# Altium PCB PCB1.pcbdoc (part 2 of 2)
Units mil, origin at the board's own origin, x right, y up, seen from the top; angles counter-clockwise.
Board outline 1377.9 x 2559.1 mil, 4 copper layers (Top Layer, Inner1, Inner2, Bottom Layer), stack 62.5 mil thick; 243 components, 192 nets, 1028 pads, 96 vias.
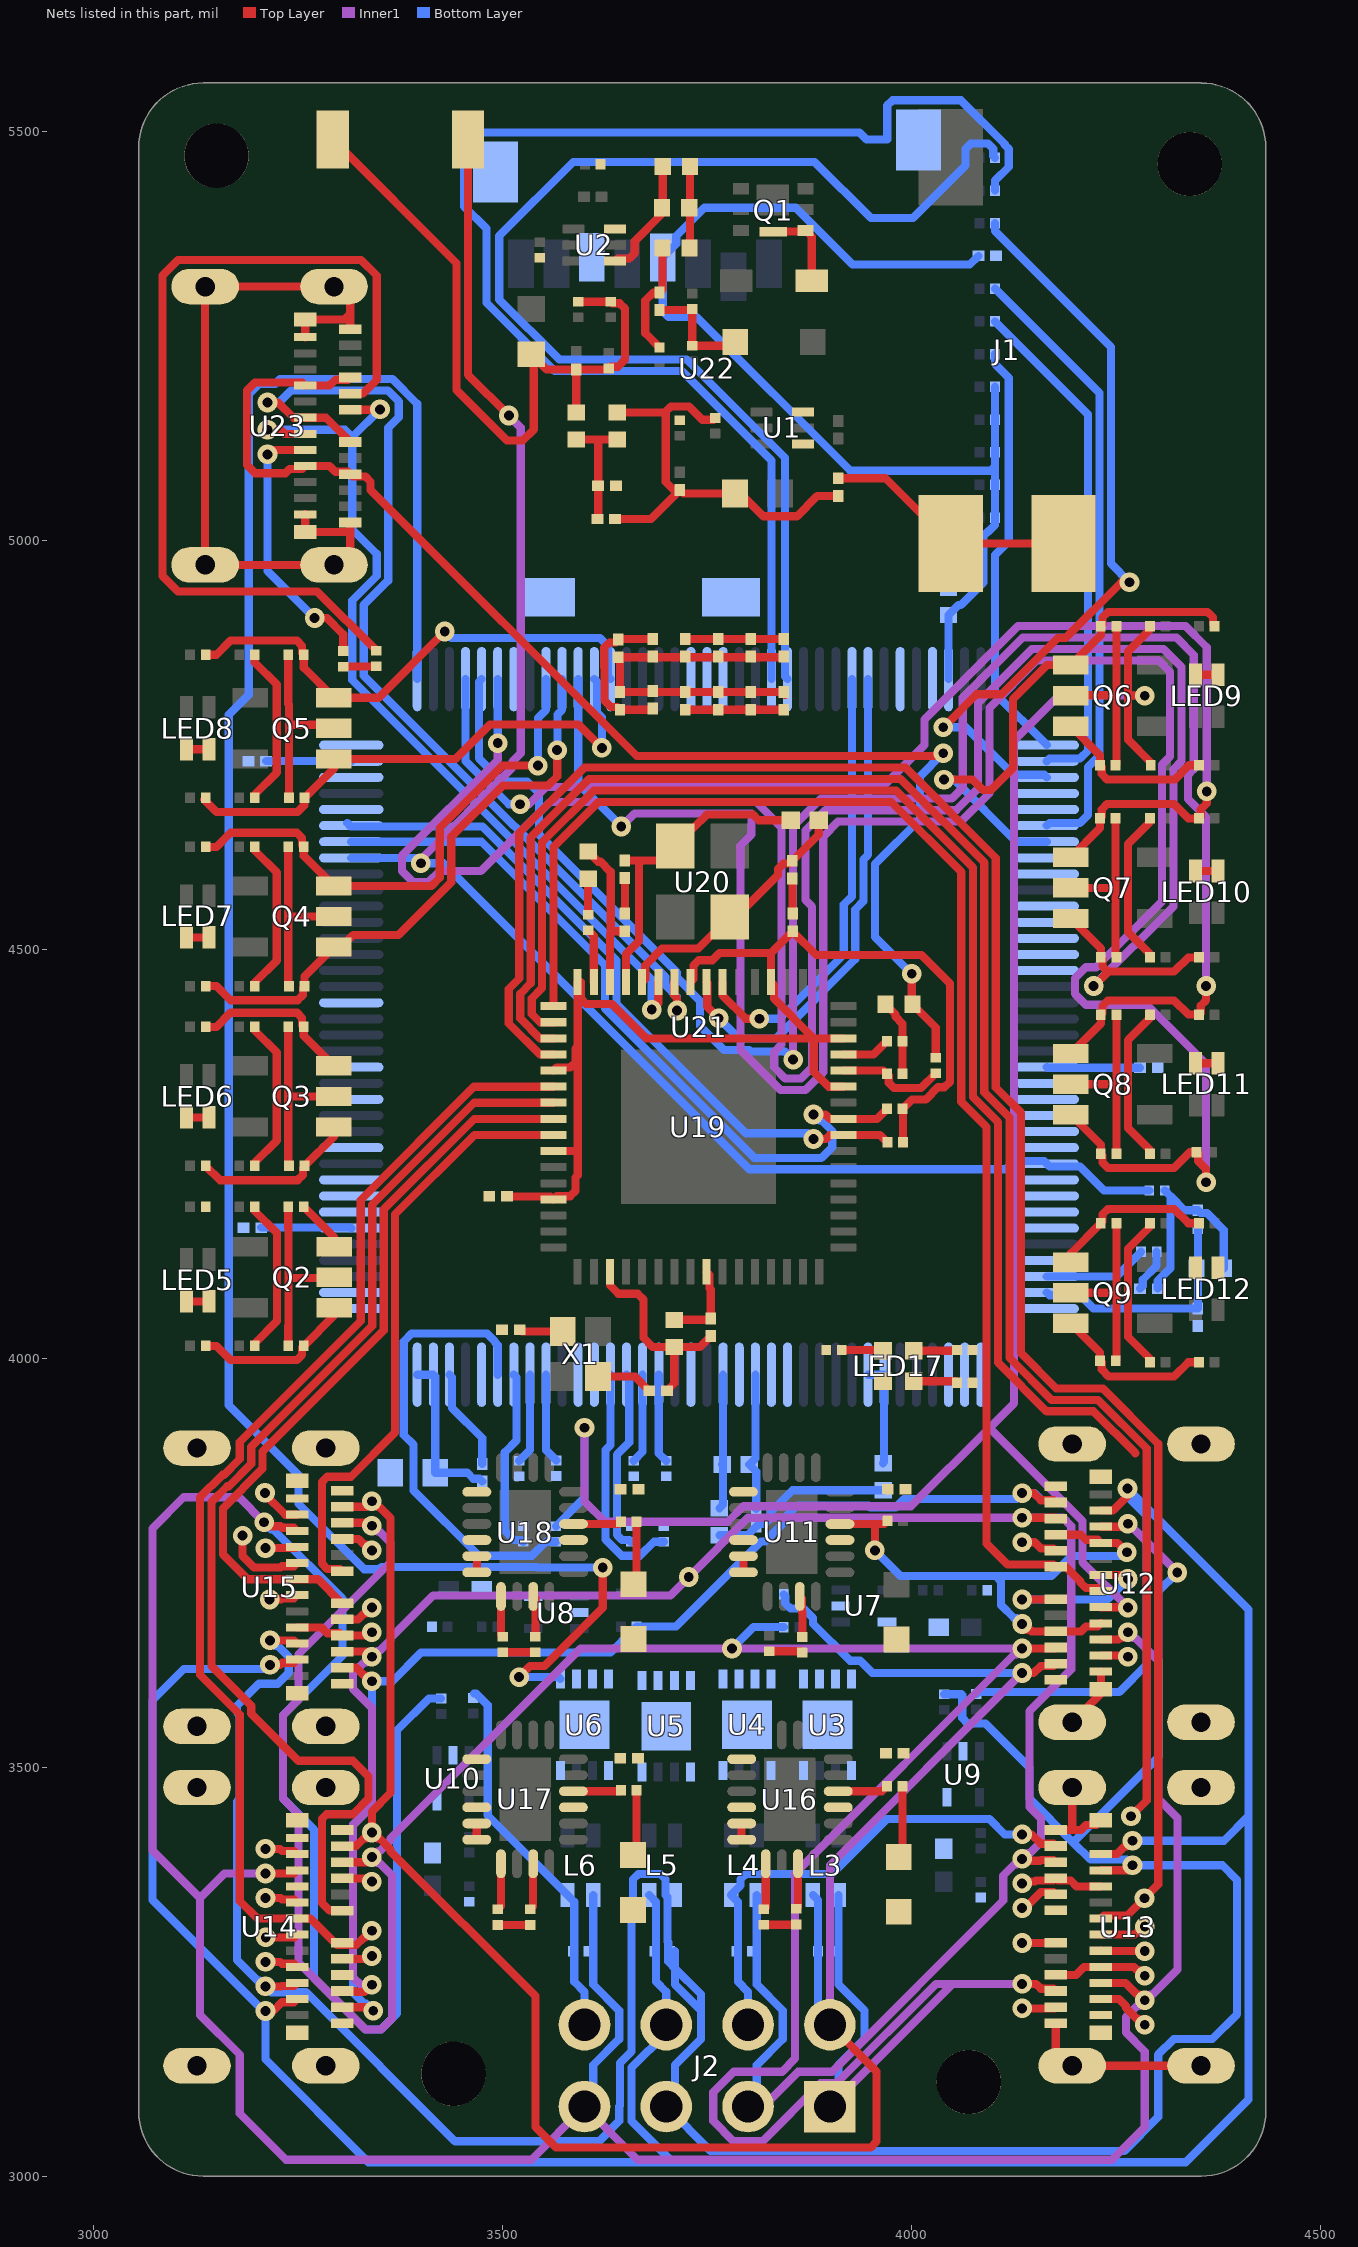
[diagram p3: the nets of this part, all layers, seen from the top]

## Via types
v1: diameter 24, hole 12, Top Layer to Bottom Layer, 96 vias

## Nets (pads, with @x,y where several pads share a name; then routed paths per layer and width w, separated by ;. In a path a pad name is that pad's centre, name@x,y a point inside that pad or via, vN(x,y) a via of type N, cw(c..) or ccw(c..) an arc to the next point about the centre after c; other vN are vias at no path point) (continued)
$1N25057: R81.2 U11.4 U12.A4 U12.A9 U12.B4 U12.B9 | length 699.3
  Top Layer w10: U11.4@3912.2,3797.2 3952.6,3797.2 ; v1(3954.8,3765) 3954.8,3795.1 3952.6,3797.2 ; R81.2@3970.3,3801.4 3966.2,3797.2 3952.6,3797.2 ; v1(4134.8,3675) 4141.8,3668 4144.3,3668 4146.3,3666 U12.A4@4176,3666 4206.8,3666 4212.8,3672 4227.3,3672 U12.B9@4231.1,3675.8 ; U12.A9@4176,3784.1 4206.6,3784.1 4212.8,3778 4227.3,3778 U12.B4@4231.1,3774.2 4251.3,3774.2 v1(4262.9,3762.7)
  Bottom Layer w10: v1(3954.8,3765) 3986.2,3733.6 4102.8,3733.6 ; v1(4134.8,3675) 4127.8,3682 4125.2,3682 4109.2,3698 4109.2,3727.2 4102.8,3733.6 ; v1(4262.9,3762.7) 4258.2,3758 4195,3758 4170.6,3733.6 4102.8,3733.6
$1N25065: R84.2 U13.A4 U13.A9 U13.B4 U13.B9 U16.4 | length 282.5
  Top Layer w10: U16.4@3910,3470.5 3963.4,3470.5 R84.2@3969.6,3476.7 ; v1(4134.8,3357.8) 4137,3360 4150.6,3360 4151.9,3361.3 4157.6,3361.3 4157.7,3361.3 4173.2,3361.3 U13.A9@4176,3364.1 4178.8,3361.3 4194.3,3361.3 4201.4,3354.2 U13.B4@4231.1,3354.2 ; U13.A4@4176,3246 4200.8,3246 4210.6,3255.8 U13.B9@4231.1,3255.8 4271.5,3255.8 4275.2,3252 4277.8,3252 v1(4284.8,3245)
$1N25090: LED14.1 R84.1 | length 88.4
  Top Layer w10: LED14.1@3984.1,3390.2 3988.6,3394.7 R84.1@3988.6,3476.7
$1N25091: R83.1 U16.17 | length 56.7
  Top Layer w10: R83.1@3819.1,3326.2 3821.4,3328.5 U16.17@3821.4,3381.9
$1N25094: R90.2 U15.A4 U15.A9 U15.B4 U15.B9 U18.4 | length 237.7
  Top Layer w10: v1(3209.7,3767.8) 3247,3767.8 U15.B9@3248.4,3769.2 ; U15.B4@3248.4,3670.8 3278.1,3670.8 3285.2,3663.7 3300.7,3663.7 U15.A9@3303.5,3660.9 3335.6,3660.9 v1(3339.8,3665) ; U15.A4@3303.5,3779 3323.3,3779 3330.2,3772 3332.8,3772 v1(3339.8,3765) ; U18.4@3586.3,3797.3 3641.5,3797.3 R90.2@3644.3,3800
$1N25095: R87.2 U14.A4 U14.A9 U14.B4 U14.B9 U17.4 | length 138.1
  Top Layer w10: v1(3209.7,3261.9) 3227.8,3261.9 3230.1,3259.6 3244.6,3259.6 U14.B4@3248.4,3255.8 ; U14.A4@3303.5,3364 3335.8,3364 v1(3339.8,3360) ; U17.4@3586.2,3470.5 3642.9,3470.5 R87.2@3644.5,3472
$1N25144: LED16.1 R90.1 | length 77.9
  Top Layer w10: LED16.1@3659.8,3723.5 3663.3,3727 R90.1@3663.3,3800
$1N25145: LED15.1 R87.1 | length 81.4
  Top Layer w10: LED15.1@3659.2,3392.4 3663.5,3396.7 R87.1@3663.5,3472
$1N25146: R89.1 U18.17 | length 50.1
  Top Layer w10: U18.17@3497.7,3708.7 3497.7,3661.6 R89.1@3499.8,3659.5
$1N25147: R86.1 U17.17 | length 57.6
  Top Layer w10: R86.1@3493.5,3326.1 3497.7,3330.2 U17.17@3497.7,3381.9
$1N25148: LED17.4 R93.1 | length 50.9
  Top Layer w10: R93.1@3914.3,4010 3963.9,4010 LED17.4@3964.9,4009.1
$1N25149: LED17.3 R92.1 | length 53.3
  Top Layer w10: LED17.3@4002.3,4009.1 4054.3,4009.1 R92.1@4055.3,4010
$1N25150: LED17.2 R91.2 | length 53.7
  Top Layer w10: LED17.2@4002.3,3971.7 4053.6,3971.7 R91.2@4055.3,3970
$1N25179: R94.1 U21.28 | length 110
  Bottom Layer w10: U21.28@3552.8,3979.8 3552.8,3887.5 R94.1@3565.3,3875
$1N25180: R95.1 U21.29 | length 110.8
  Bottom Layer w10: R95.1@3519.8,3874.5 3533.1,3887.8 U21.29@3533.1,3979.8
$1N25181: R96.1 U21.30 | length 226
  Bottom Layer w10: U21.30@3513.4,3979.8 3516.6,3976.6 3516.6,3899.2 3502.4,3885 3502.4,3789 3513.8,3777.6 3522.7,3777.6 R96.1@3524.8,3775.5
$1N25182: R97.1 U21.31 | length 563.1
  Bottom Layer w10: U21.31@3493.7,3979.8 3493.7,4016.2 3490.5,4019.4 3490.5,4020.5 3480.8,4030.2 3388.4,4030.2 3378.8,4020.5 3378.8,3906.2 3390.6,3894.4 3390.6,3838.4 3470.5,3758.5 3535.7,3758.5 3552.6,3775.5 R97.1@3564.8,3775.5
$1N25226: R98.1 U21.21 | length 109.1
  Bottom Layer w10: U21.21@3690.6,3979.8 3690.6,3883.7 R98.1@3699.8,3874.5
$1N25227: R99.1 U21.22 | length 109.9
  Bottom Layer w10: R99.1@3659.8,3874.5 3670.9,3885.6 U21.22@3670.9,3979.8
$1N25228: R100.1 U21.23 | length 224.3
  Bottom Layer w10: U21.23@3651.2,3979.8 3654.4,3976.6 3654.4,3897 3639.4,3882 3639.4,3784 3645.8,3777.6 3654.7,3777.6 R100.1@3656.8,3775.5
$1N25229: R101.1 U21.24 | length 290.8
  Bottom Layer w10: U21.24@3631.5,3979.8 3631.5,3893.9 3625.4,3887.8 3625.4,3778.2 3645,3758.5 3667.7,3758.5 3684.6,3775.5 R101.1@3696.8,3775.5
$1N25245: R102.1 U21.142 | length 127.7
  Bottom Layer w10: U21.142@4165,4099.9 4250.1,4099.9 R102.1@4280.3,4130
$1N25278: C44.1
$1N25293: R115.1 U23.A5 | length 1111.4
  Top Layer w10: U23.A5@3313.5,5179.3 3329.1,5179.3 3345.8,5196 3345.8,5323.6 3326.7,5342.7 3102.8,5342.7 3083.7,5323.6 3083.7,4956.4 3102.8,4937.3 3273,4937.3 R115.1@3345.3,4865
$1N25294: R116.2 U23.B5 | length 329.1
  Top Layer w10: v1(3212.2,5105) 3217.7,5110.5 U23.B5@3258.4,5110.5 ; v1(3269.8,4905) 3284.8,4905 3304.8,4885 R116.2@3304.8,4864.5
  Bottom Layer w10: v1(3212.2,5105) 3212.2,4962.5 v1@3264.8,4910
$1N25317: R117.1 U19.63 | length 66.2
  Top Layer w10: R117.1@3604.2,4523.2 3611.2,4516.2 U19.63@3611.2,4459.9
$1N25319: C53.1 R118.1 U19.60 U20.1 | length 322
  Top Layer w10: U19.60@3670.3,4459.9 3674.1,4463.7 3674.1,4480.2 3694.7,4500.9 3738.9,4500.9 3777.4,4539.4 U20.1@3777.6,4539.4 3785.1,4539.4 3836.4,4590.8 3836.4,4598.3 3842.9,4604.8 3850.4,4604.8 C53.1@3853.8,4608.1 3886.2,4640.5 R118.1@3886.2,4657.7
$1N25320: C45.1 R118.2 U19.61 U20.3 | length 385.6
  Top Layer w10: C45.1@3649.2,4608.5 3670,4608.5 ; U19.61@3650.6,4459.9 3650.6,4494.2 3666.5,4510.1 3666.5,4605 3670,4608.5 ; R118.2@3852.1,4657.7 3812.7,4657.7 3805.8,4664.6 3749.5,4664.6 3742.6,4657.7 3742.4,4657.7 U20.3@3710.7,4626 3693.2,4608.5 3670,4608.5
$1N25323: R119.2 U19.45 | length 60.2
  Top Layer w10: U19.45@3916.3,4371.3 3953.2,4371.3 R119.2@3969.7,4387.7
$1N25345: C49.2 C50.2 U19.25 | length 104.6
  Top Layer w10: C49.2@3709.5,4046.9 3752.6,4046.9 C50.2@3754.2,4048.5 3754.2,4083.9 3752.8,4085.3 3752.8,4101.8 U19.25@3749,4105.6
+3V3: C8.2 C9.1 C10.2 C15.2 C18.2 C21.2 C24.2 C30.2 C31.2 C32.2 C33.2 C34.2 C35.2 C44.2 C46.2 C47.2 L2.2 L8.1 LED17.1 R6.2 R7.2 R8.2 R102.2 R104.2 R105.2 R106.2 R107.2 R108.2 R120.1 R121.1 SW1.1 U3.5 U4.5 U5.5 U6.5 U19.5 U19.10 U19.13 U19.43 U19.46 U19.52 U19.57 U19.64 U21.7 U21.8 U21.13 U21.16 U21.19 U21.32 U21.42 U21.56 U21.71 U21.79 U21.90 U21.91 U21.92 U21.106 U21.119 U21.129 U21.144 U22.4 | length 4593.6
  Top Layer w10: SW1.1@3292.1,5490 3443.4,5338.7 3443.4,5183.8 3505.2,5122 3524.3,5122 3537.8,5135.5 L2.2@3537.8,5224.5 ; C47.2@3505,4197.7 3558.4,4197.7 U19.13@3562,4194.2 3565.8,4197.9 3582.3,4197.9 3588.7,4204.4 3588.7,4220.9 3591.5,4223.7 3591.5,4253.9 ; L2.2@3534.8,5227.4 L2.2@3537.8,5224.5 ; U19.10@3562,4253.2 3590.8,4253.2 3591.5,4253.9 ; U19.5@3562,4351.6 3565.8,4355.4 3582.3,4355.4 3588.7,4361.8 3588.7,4378.4 3591.5,4381.2 ; C8.2@3589.6,5156.1 C10.2@3589.6,5208.8 ; R7.2@3591.9,5291.7 R6.2@3631.9,5291.7 3634,5289.7 3642.8,5289.7 3649.3,5283.2 3649.3,5220.8 3640.6,5212.1 3631.7,5212.1 R8.2@3629.6,5210.1 3628.4,5208.8 C10.2@3589.6,5208.8 ; C18.2@3683.2,4794.3 3681.6,4792.7 C21.2@3643.2,4792.7 3639.9,4796 3632.3,4796 3624.4,4804 3624.4,4844.6 3623.9,4845.1 3623.9,4868.7 3630.4,4875.1 3637.9,4875.1 C15.2@3641.3,4878.5 3642.1,4879.3 C24.2@3683.2,4879.3 ; U19.57@3729.3,4459.9 3733.1,4463.7 3733.1,4480.2 3739.5,4486.6 3756.1,4486.6 3765,4495.5 3827.8,4495.5 ; U19.43@3916.3,4331.9 3898.2,4331.9 3880.1,4350 3880.1,4391 ; U19.46@3916.3,4391 3880.1,4391 ; R121.1@3989.2,4263.9 3989.2,4304.3 R120.1@3988.7,4304.8 4000.3,4316.4 4017.1,4316.4 4032,4331.3 4040.1,4331.3 4046.5,4337.7 4046.5,4458.2 4011.8,4493 3883.1,4493 C46.2@3854.2,4521.9 3827.8,4495.5 ; L2.2@3537.8,5224.5 3553.4,5208.8 C10.2@3589.6,5208.8 ; 3591.5,4253.9 3591.5,4381.2 ; 3591.5,4381.2 U19.64@3591.5,4459.9 3595.3,4459.9 3595.3,4439.6 3601.8,4433.2 3633.3,4433.2 3675.4,4391 3880.1,4391 ; 3827.8,4495.5 U19.52@3827.8,4459.9 3831.5,4456.1 3831.5,4439.6 3880.1,4391
  Bottom Layer w10: C34.2@3204.6,4159.6 3313.9,4159.6 U21.42@3314.6,4158.9 ; C33.2@3210.6,4730 3314.4,4730 U21.71@3314.6,4729.8 ; U21.8@3946.5,3979.8 U21.7@3966.1,3979.8 3966.1,3872.9 C31.2@3964.8,3871.5 ; U21.106@4044.9,4830.2 4044.8,4830.3 C30.2@4044.8,4908.5 4057,4920.7 4059.9,4920.7 4087.6,4948.4 4087.6,5005.5 4092.4,5010.3 4093.2,5010.3 4101.7,5018.8 R105.2@4101.7,5027.6 R104.2@4101.7,5067.6 4101.7,5090.4 ; C44.2@4081.4,5347.6 4070.8,5337 3927.5,5337 3858,5406.6 3746.4,5406.6 3712,5372.1 3712,5362.4 U22.4@3695.4,5345.8 3695.4,5280 3702.5,5272.9 3736.8,5272.9 3924.8,5085 4096.3,5085 4101.7,5090.4 ; R106.2@4101.7,5187.6 R107.2@4101.7,5147.6 R108.2@4101.7,5107.6 4101.7,5090.4 ; U21.129@4165,4355.8 4165.8,4355 C35.2@4279,4355 ; C32.2@4279,4085 4282.3,4088.4 4282.3,4095.9 4299.3,4112.9 R102.2@4299.3,4130
+5V: C1.2 C2.2 C3.1 C4.2 C12.1 C13.2 C14.2 C17.2 C20.2 C23.2 L1.2 R1.2 R10.2 R17.2 R21.2 R25.2 R29.2 U2.1 U3.3 U4.3 U5.3 U6.3 | length 817.8
  Top Layer w10: U2.1@3636.9,5341.4 3639.4,5343.8 3639.6,5343.8 3640.3,5344.5 3654.9,5344.5 3661.3,5351 3661.3,5365.7 3694.7,5399.2 C1.2@3694.7,5406.7 3695.5,5407.5 C2.2@3695.5,5457 ; C12.1@3637.3,5026 3681.1,5026 C4.2@3716.5,5061.5 ; C13.2@3639.6,5156.1 3698,5156.1 3699.1,5157.3 ; C23.2@3723.2,4792.7 C20.2@3763.2,4792.7 C17.2@3803.2,4792.7 C14.2@3843.2,4792.7 ; R1.2@3759.8,5149.5 3757.7,5147.4 3743.7,5147.4 3727.4,5163.7 3705.6,5163.7 3699.1,5157.3 ; C3.1@3909.8,5054.2 3884.3,5054.2 3859.4,5029.3 3818.8,5029.3 3793.8,5054.2 3787,5054.2 L1.2@3783.9,5057.3 3720.7,5057.3 C4.2@3716.5,5061.5 ; 3699.1,5157.3 3699.1,5071.3 3708.9,5061.5 C4.2@3716.5,5061.5
+12V: C6.1 C7.2 C16.2 C19.2 C22.2 C25.2 C26.2 C27.2 C28.2 C29.2 D1.1 Q1.4 Q1.8 R4.1 U1.1 U7.5 U8.5 U9.5 U10.5 U11.11 U16.11 U17.11 U18.11 | length 366.5
  Top Layer w10: R4.1@3691.5,5235.8 3674.1,5253.2 3674.1,5293.3 3683.9,5303.1 C6.1@3691.5,5303.1 3695,5306.5 C7.2@3695,5357.3 ; C16.2@3723.2,4879.3 C19.2@3763.2,4879.3 C22.2@3803.2,4879.3 C25.2@3843.2,4879.3 ; Q1.8@3830.6,5377.4 3868.6,5377.4 Q1.4@3870,5378.8 3877.7,5371.1 D1.1@3877.7,5317.3
BTN: R103.2 SW1.2 U21.65 U21.135 | length 2114.7
  Top Layer w10: SW1.2@3457.4,5490 3457.4,5202.3 v1(3507.3,5152.5)
  Inner1 w10: v1(3399.8,4605) 3399.8,4610 3511.8,4722 3511.8,4729.5 3521.8,4739.5 3521.8,5138 v1(3507.3,5152.5)
  Bottom Layer w10: U21.65@3314.6,4611.7 3393.1,4611.7 v1(3399.8,4605) 3427.5,4605 3801.6,4230.9 4114.3,4230.9 4124.3,4240.9 4161.8,4240.9 U21.135@4165,4237.7 4168.2,4234.5 4205.7,4234.5 4235.1,4205 R103.2@4290.3,4205
CAN0_EN: U3.8 U21.134
CAN0_H: J2.2 L3.4 R11.2 R15.1 U12.A2 U13.A2 U14.A2 U15.A2 | length 2671.9
  Top Layer w10: U14.A2@3303.5,3403.4 3320.7,3403.4 3330.2,3413 3332.8,3413 v1(3339.8,3420) ; U15.A2@3303.5,3818.4 3333.2,3818.4 v1(3339.8,3825) 3346.8,3818 3349.3,3818 3362.8,3804.5 3362.8,3468.7 3339.8,3445.7 v1(3339.8,3420) ; J2.2@3899.8,3185 3956.8,3127.9 3956.8,3042.1 3949.8,3035 3564.8,3035 3539.8,3060 3539.8,3220 3362.8,3397 3362.8,3399.5 3349.3,3413 3346.8,3413 v1(3339.8,3420) ; v1(4134.8,3205) 4174.4,3205 U13.A2@4176,3206.6 ; v1(4134.8,3615) 4148.9,3615 4157.7,3623.8 4173.2,3623.8 U12.A2@4176,3626.6
  Inner1 w10: J2.2@3899.8,3185 3899.8,3380 v1(4134.8,3615)
  Bottom Layer w10: R15.1@3843.3,3711.2 3845.3,3709.2 3845.3,3700.3 3851.8,3693.9 3867.5,3693.9 3879.2,3682.2 3879.2,3675.3 3924.4,3630.1 3936.6,3630.1 3951.7,3615 v1(4134.8,3615) ; L3.4@3879,3343.6 3885.3,3337.3 R11.2@3885.3,3275 3885.3,3199.5 J2.2@3899.8,3185
CAN0_L: J2.1 L3.3 R11.1 R16.1 U12.A3 U13.A3 U14.A3 U15.A3 | length 3848.4
  Top Layer w10: U14.A3@3303.5,3383.7 3333.5,3383.7 v1(3339.8,3390) ; U15.A3@3303.5,3798.7 3336,3798.7 v1(3339.8,3795) ; v1(4134.8,3235) 4151.8,3235 4157.7,3229.1 4173.1,3229.1 U13.A3@4176,3226.3 ; v1(4134.8,3645) 4174.7,3645 U12.A3@4176,3646.3
  Inner1 w10: v1(3339.8,3795) 3346.8,3788 3349.3,3788 3362.8,3774.5 3362.8,3750.5 3250.3,3638 3250.3,3582.6 3231.1,3563.4 3231.1,3461.6 3250.3,3442.4 3250.3,3260.9 3332,3179.2 3351.1,3179.2 3364.5,3192.6 3364.5,3367.7 3349.3,3383 3346.8,3383 v1(3339.8,3390) 3346.8,3397 3349.3,3397 3362.8,3410.5 3362.8,3413 3594.8,3645 v1(3780.2,3645) v1(4134.8,3645) 4127.8,3638 4125.2,3638 3857.3,3370 3857.3,3143.7 3841.1,3127.5 3782.2,3127.5 3757.3,3102.6 3757.3,3067.4 3782.2,3042.5 3817.4,3042.5 3888.3,3113.5 3908.1,3113.5 4029.7,3235 4049.8,3235 ; J2.1@3899.8,3085 4049.8,3235 ; v1(4134.8,3235) 4049.8,3235
  Bottom Layer w10: v1(3780.2,3645) 3806.4,3671.2 R16.1@3843.3,3671.2 ; J2.1@3899.8,3085 3910.5,3095.8 3910.5,3135.7 3942.2,3167.4 3942.2,3202.6 3910.5,3234.3 L3.3@3910.5,3343.6
CAN0_RX: U3.4 U21.136
CAN0_TX: U3.1 U21.137
CAN1_EN: U4.8 U21.130
CAN1_H: J2.4 L4.4 R12.2 R19.1 U12.A11 U13.A11 U14.A11 U15.A11 | length 2100.5
  Top Layer w10: U14.A11@3303.5,3206.5 3337.2,3206.5 v1(3341.5,3202.2) ; U15.A11@3303.5,3621.5 3320.8,3621.5 3330.2,3612 3332.8,3612 v1(3339.8,3605) ; v1(4134.8,3417.8) 4146.2,3417.8 4157.7,3406.3 4173.2,3406.3 U13.A11@4176,3403.5 ; v1(4134.8,3835) 4149,3835 4157.7,3826.3 4173.2,3826.3 U12.A11@4176,3823.5
  Bottom Layer w10: v1(3341.5,3202.2) 3332.8,3211 3330.2,3211 3316.8,3224.4 3316.8,3429.5 3339.8,3452.5 v1(3339.8,3605) 3364.8,3605 3399.8,3640 3631.5,3640 3646,3654.5 3654.9,3654.5 3661.3,3661 3661.3,3669.8 R19.1@3663.4,3671.9 3711.7,3671.9 3815.7,3776 3820.7,3776 3841.1,3796.4 3841.1,3801.4 3859.8,3820 3947.2,3820 3949.6,3817.6 3979.9,3817.6 3990.3,3828 4127.8,3828 v1(4134.8,3835) 4149.8,3835 4157.8,3827 ; J2.4@3799.8,3185 3799.8,3225.3 3787.3,3237.7 3787.3,3335.3 L4.4@3779,3343.6 3790.7,3355.3 3790.7,3362.9 3797.1,3369.3 3902.6,3369.3 3969.7,3436.5 4094.9,3436.5 4113.6,3417.8 v1(4134.8,3417.8)
CAN1_L: J2.3 L4.3 R12.1 R20.1 U12.A10 U13.A10 U14.A10 U15.A10 | length 2756.6
  Top Layer w10: U14.A10@3303.5,3226.2 3318.9,3226.2 3320.2,3224.9 3330.8,3224.9 v1(3339.8,3234) ; U15.A10@3303.5,3641.2 3333.6,3641.2 v1(3339.8,3635) ; v1@4134.8,3385.5 4156.6,3385.5 4157.7,3386.6 4173.2,3386.6 U13.A10@4176,3383.8 ; v1(4134.8,3805) 4174.8,3805 U12.A10@4176,3803.8
  Inner1 w10: v1(3339.8,3234) 3325.8,3234 3316.8,3243 3316.8,3429.5 3339.8,3452.5 3339.8,3572.5 3316.8,3595.5 3316.8,3614.5 3330.2,3628 3332.8,3628 v1(3339.8,3635) 3346.8,3642 3349.3,3642 3362.8,3655.5 3362.8,3658 3414.8,3710 3704.8,3710 v1(3727.3,3732.5) 3799.8,3805 v1(4134.8,3805) 4184.8,3805 4194.8,3795 4194.8,3619.5 4143.7,3568.4 4143.7,3451.4 4157.8,3437.3 4157.8,3408.2 4144.3,3394.8 4141.8,3394.8 v1(4134.8,3387.8) 4127.8,3380.8 4125.2,3380.8 4111.8,3367.3 4111.8,3336.9 3902.3,3127.5 3860.9,3127.5 3818.4,3085 J2.3@3799.8,3085
  Bottom Layer w10: J2.3@3799.8,3085 3810.5,3095.8 3810.5,3135.7 3842.2,3167.4 3842.2,3202.6 3810.5,3234.3 L4.3@3810.5,3343.6
CAN1_RX: U4.4 U21.132
CAN1_TX: U4.1 U21.133
CAN2_EN: U5.8 U21.121
CAN2_H: J2.6 L5.4 R13.2 R23.1 U12.B2 U13.B2 U14.B2 U15.B2 | length 3904.1
  Top Layer w10: v1(3209.8,3201.9) 3219.3,3201.9 3230.1,3212.6 3244.6,3212.6 U14.B2@3248.4,3216.4 ; v1(3215.3,3625) 3227.5,3625 3230.1,3627.6 3244.6,3627.6 U15.B2@3248.4,3631.4 ; U13.B2@4231.1,3393.6 4250.8,3393.6 4260.2,3403 4262.8,3403 v1(4269.8,3410) ; U12.B2@4231.1,3813.6 4245.7,3813.6 4263.7,3831.6 v1(4263.7,3840.6)
  Bottom Layer w10: v1@3209.8,3201.8 3209.8,3142.8 3335.7,3016.8 3707.9,3016.8 ; v1(3209.8,3201.9) 3207.3,3201.9 3071.6,3337.5 3071.6,3581.8 3109.8,3620 3210.3,3620 v1(3215.3,3625) ; L5.4@3679,3343.6 3687.3,3335.3 3687.3,3237.7 3699.8,3225.3 J2.6@3699.8,3185 3699.8,3175.1 3657.3,3132.6 3657.3,3067.4 3707.9,3016.8 ; R23.1@4079,3589.5 4081.5,3592 4253.7,3592 4287.2,3625.5 4287.2,3807.2 4263.7,3830.7 v1(4263.7,3840.6) 4411.5,3692.7 4411.5,3440 ; v1(4269.8,3410) 4381.5,3410 4411.5,3440 ; 3707.9,3016.8 4334.8,3016.8 4411.5,3093.6 4411.5,3440
CAN2_L: J2.5 L5.3 R13.1 R24.1 U12.B3 U13.B3 U14.B3 U15.B3 | length 3868.1
  Top Layer w10: v1(3209.8,3231.9) 3229.6,3231.9 3230.1,3232.3 3244.7,3232.3 U14.B3@3248.4,3236.1 ; v1(3215.3,3655) 3230,3655 3230.1,3654.9 3244.7,3654.9 U15.B3@3248.4,3651.1 ; U13.B3@4231.1,3373.9 4263.7,3373.9 v1(4269.8,3380) ; U12.B3@4231.1,3793.9 4260.5,3793.9 v1(4264.2,3797.6)
  Inner1 w10: v1(4264.2,3797.6) 4264.8,3797.6 v1(4324.6,3737.9)
  Bottom Layer w10: v1(3215.3,3655) 3222.3,3648 3224.8,3648 3238.3,3634.5 3238.3,3615.5 3224.8,3602 3201.8,3602 3174.8,3575 3174.8,3567 3178.3,3563.4 3178.3,3461.6 3174.8,3458 3174.8,3264.3 3200.2,3238.9 3202.8,3238.9 v1(3209.8,3231.9) 3216.8,3224.8 3259.4,3224.8 3441.7,3042.5 3617.4,3042.5 3642.2,3067.4 3642.2,3085 3643.3,3086 3643.3,3138.4 3657.3,3152.5 3657.3,3322.3 3659.2,3324.3 3659.2,3362.9 3665.6,3369.3 3692.4,3369.3 3698.8,3362.9 3698.8,3343.6 3701.3,3341.1 3701.3,3286.8 3702.2,3285.9 3702.2,3262.3 3710.5,3254 ; 3710.5,3275 3710.5,3254 ; R24.1@4039.5,3589 4060.7,3589 4061.7,3588.1 4061.7,3560 4068.1,3553.5 4089.9,3553.5 4143.7,3499.7 4143.7,3461.6 4197.3,3408 ; v1(4324.6,3737.9) 4301.2,3714.5 4301.2,3512 4197.3,3408 ; 3710.5,3254 3710.5,3234.3 3742.2,3202.6 ; 3710.5,3254 3742.2,3222.3 3742.2,3202.6 ; 3742.2,3202.6 3742.2,3167.4 3710.5,3135.7 3710.5,3095.8 J2.5@3699.8,3085 3753.9,3030.8 4259.8,3030.8 4301.2,3072.3 4301.2,3148.4 4320.3,3167.6 4367.3,3167.6 4397.5,3197.8 4397.5,3362.2 4379.8,3380 v1(4269.8,3380) 4262.8,3387 4218.3,3387 4197.3,3408
CAN2_RX: U5.4 U21.123
CAN2_TX: U5.1 U21.122
CAN3_EN: U6.8 U21.131
CAN3_H: J2.8 L6.4 R14.2 R27.1 U12.B11 U13.B11 U14.B11 U15.B11 | length 657.1
  Top Layer w10: v1(3209.2,3835.3) 3209.2,3833.2 3233.9,3808.6 U15.B11@3248.4,3808.6 ; v1(3209.8,3400) 3227.5,3400 3230.1,3397.4 3244.7,3397.4 U14.B11@3248.4,3393.6 ; U13.B11@4231.1,3216.4 4253.3,3216.4 4261.8,3208 4261.8,3205.5 4275.2,3192 4277.8,3192 v1(4284.8,3185) ; U12.B11@4231.1,3636.4 4262.8,3636.4 v1(4264.2,3635)
  Bottom Layer w10: R27.1@3464.8,3590 3467.4,3590 3481.4,3576 3481.4,3441.2 L6.4@3579,3343.6 3587.3,3335.3 3587.3,3237.7 3599.8,3225.3 J2.8@3599.8,3185
CAN3_L: J2.7 L6.3 R14.1 R28.1 U12.B10 U13.B10 U14.B10 U15.B10 | length 4557.1
  Top Layer w10: v1(3208.1,3799.3) 3212.8,3794.6 3228.2,3794.6 3230.1,3792.7 3244.6,3792.7 U15.B10@3248.4,3788.9 ; v1(3209.8,3370) 3230,3370 3230.1,3370.1 3244.7,3370.1 U14.B10@3248.4,3373.9 ; U13.B10@4231.1,3236.1 4261.1,3236.1 4275.2,3222 4277.8,3222 v1(4284.8,3215) ; U12.B10@4231.1,3656.1 4252.8,3656.1 4254.7,3658 4257.2,3658 v1(4264.2,3665)
  Inner1 w10: v1(3208.1,3799.3) 3177.4,3830 3109.8,3830 3071.6,3791.8 3071.6,3398.2 3129.8,3340 ; v1(3209.8,3370) 3159.8,3370 3129.8,3340 ; v1(4264.2,3665) 4271.2,3658 4273.7,3658 4301.2,3630.5 4301.2,3461.6 4324.8,3438 4324.8,3252.5 4294.3,3222 4291.8,3222 v1(4284.8,3215) 4277.8,3208 4275.2,3208 4261.8,3194.5 4261.8,3175.5 4284.8,3152.5 4284.8,3060 4244.8,3020 3664.8,3020 J2.7@3599.8,3085 3534.8,3020 3234.8,3020 3178.3,3076.5 3178.3,3148.4 3129.8,3197 3129.8,3340
  Bottom Layer w10: v1(3208.1,3799.3) 3216.6,3790.8 3219.2,3790.8 3303.9,3706.2 3303.9,3636.2 3231.1,3563.4 3231.1,3461.6 3269,3423.7 3269,3242.2 3332,3179.2 3351.1,3179.2 3370.6,3198.7 3370.6,3545.1 3409.5,3584 R28.1@3424.5,3584 ; J2.7@3599.8,3085 3610.5,3095.8 3610.5,3135.7 3642.2,3167.4 3642.2,3202.6 3610.5,3234.3 L6.3@3610.5,3343.6
CAN3_RX: U6.4 U21.72
CAN3_TX: U6.1 U21.73 | length 2608.5
  Top Layer w10: v1(3519.8,3610) 3533.3,3623.5 3550.7,3623.5 3622,3694.8 v1(3622,3743.9)
  Bottom Layer w10: U21.73@3395.3,4830.2 3395.3,5166.8 3365.1,5197 3227.4,5197 3221.8,5191.4 3202.7,5191.4 3189.2,5177.9 3189.2,4811 3164.8,4786.6 3164.8,3942.9 3250.3,3857.4 3250.3,3822 3330.2,3742 3349.3,3742 3351.8,3744.5 3541.5,3744.5 3542.1,3743.9 v1(3622,3743.9) ; v1(3519.8,3610) 3567.9,3610 U6.1@3570.2,3607.6
CH1_D_N: U12.A7 U12.B7 U19.1 | length 1749.9
  Top Layer w10: U19.1@3562,4430.4 3562,4625 3617,4680 3974.8,4680 4060.5,4594.2 4060.5,4313.4 4091.2,4282.7 4091.2,3773.5 4117.2,3747.6 4173.2,3747.6 U12.A7@4176,3744.8 4188.7,3744.8 4206.3,3727.2 4206.3,3725.4 4212.8,3718.9 4227.3,3718.9 U12.B7@4231.1,3715.2
CH1_D_P: U12.A6 U12.B6 U19.2 | length 1885.9
  Top Layer w10: U19.2@3562,4410.7 3545.5,4410.7 3535.3,4420.9 3535.3,4439.8 3548,4452.6 3548,4630.8 3611.2,4694 3980.6,4694 4074.6,4600 4074.6,4319.2 4105.2,4288.5 4105.2,3994.7 4164.9,3935 4222,3935 4273.2,3883.8 ; v1(4134.8,3705) 4175.6,3705 U12.A6@4176,3705.4 ; U12.B6@4231.1,3734.8 4259.4,3734.8 v1(4264.2,3730)
  Bottom Layer w10: v1(4134.8,3705) 4239.2,3705 v1(4264.2,3730)
CH1_IMON: R80.1 U11.19 U21.47 | length 51.1
  Top Layer w10: U11.19@3863,3708.7 3865.8,3705.9 3865.8,3689.8 3866.3,3689.4 R80.1@3866.3,3659
CH1_PWR_EN: U11.14 U21.37
CH1_SBU1: R33.2 R34.2 R96.2 U12.A8 | length 238.2
  Top Layer w10: R33.2@3196.6,4015 3196.6,4018 3223.9,4045.3 3223.9,4152.8 3196.6,4180 R34.2@3196.6,4185 ; v1(4134.8,3775) 4149.9,3775 4157.7,3767.3 4173.2,3767.3 U12.A8@4176,3764.4
CH1_SBU1_IGN: Q2.1 R31.2 R36.2 U21.112 | length 201.5
  Top Layer w10: R36.2@3136.6,4015 3149.7,4015 3167.1,3997.6 3248.1,3997.6 3254.5,4004.1 3254.5,4012.9 R31.2@3256.6,4015 3293.6,4052 Q2.1@3293.6,4061.6
CH1_SBU1_RELAY: Q2.3 R32.2 R35.2 U21.113 | length 63.9
  Top Layer w10: R32.2@3256.6,4185 3293.6,4148 Q2.3@3293.6,4136.4
CH1_SBU2: R57.2 R58.2 R97.2 U12.B8 | length 2350.8
  Top Layer w10: U12.B8@4231.1,3695.5 4263.7,3695.5 v1(4264.2,3695) ; v1(4284.8,4810) 4266.5,4810 4264.2,4812.3 ; R57.2@4291.1,4895 4291.1,4890.7 4264.2,4863.8 4264.2,4812.3 ; R58.2@4292.1,4725 4292.1,4728.3 4264.2,4756.2 4264.2,4812.3
  Inner1 w10: v1(3599.8,3915) 3599.8,3825 3624.8,3800 3774.9,3800 3794,3819 3999,3819 4094.8,3914.8 ; v1(4264.2,3695) 4208.8,3750.4 4208.8,3800.8 4094.8,3914.8 ; v1(4284.8,4810) 4179.8,4810 4124.8,4755 4124.8,3944.8 4094.8,3914.8
  Bottom Layer w10: R97.2@3564.8,3794.5 3599.8,3829.5 v1(3599.8,3915)
CH1_SBU2_IGN: Q6.1 R56.2 R59.2 U21.115 | length 657
  Top Layer w10: v1(4039.3,4707.4) 4073.9,4707.4 4086.8,4694.5 4096.8,4694.5 4123.8,4721.5 4123.8,4805.9 4165.3,4847.4 Q6.1@4194.4,4847.4 4231.1,4884.1 R59.2@4231.1,4895 4233.2,4897.1 4233.2,4905.9 4239.6,4912.4 4361.6,4912.4 4368.1,4905.9 4368.1,4897.1 R56.2@4370.1,4895
  Bottom Layer w10: v1(4039.3,4707.4) 4051.5,4707.4 4127.5,4631.4 U21.115@4165,4631.4
CH1_SBU2_RELAY: Q6.3 R55.2 R60.2 U21.116 | length 203
  Top Layer w10: Q6.3@4194.4,4772.6 4230.1,4736.9 R60.2@4230.1,4725 4232.2,4722.9 4232.2,4714.1 4238.6,4707.6 4321.6,4707.6 4339,4725 R55.2@4351.1,4725
CH2_D_N: U13.A7 U13.B7 U19.3 | length 2251.1
  Top Layer w10: U19.3@3562,4391 3545.3,4391 3521.3,4415.1 3521.3,4445.6 3534,4458.4 3534,4636.6 3605.4,4708 3986.4,4708 4088.6,4605.8 4088.6,4325 4119.3,4294.3 4119.3,4000.5 4170.8,3949 4227.8,3949 4287.2,3889.6 4287.2,3459.2 v1(4268,3440) ; U13.B7@4231.1,3295.2 4272.4,3295.2 4275.2,3298 4277.8,3298 v1(4284.8,3305)
CH2_D_P: U13.A6 U13.B6 U19.4 | length 2469.8
  Top Layer w10: U19.4@3562,4371.3 3545.2,4371.3 3507.2,4409.3 3507.2,4451.5 3520,4464.2 3520,4642.4 3599.6,4722 3992.2,4722 4102.6,4611.6 4102.6,4330.8 4133.3,4300.1 4133.3,4006.3 4176.6,3963 4233.6,3963 4301.2,3895.4 4301.2,3356.5 v1(4284.4,3339.7) 4263.4,3318.6 4234.9,3318.6 U13.B6@4231.1,3314.8 ; v1(4134.8,3285) 4175.6,3285 U13.A6@4176,3285.4
CH2_IMON: R82.1 U16.19 U21.50 | length 56
  Top Layer w10: R82.1@3858.6,3326.8 3860.8,3329 U16.19@3860.8,3381.9
CH2_PWR_EN: U16.14 U21.38
CH2_SBU1: R40.2 R41.2 R100.2 U13.A8 | length 242.9
  Top Layer w10: R40.2@3196.6,4235 3196.6,4239.3 3223.6,4266.2 3223.6,4373.8 3196.6,4400.7 R41.2@3196.6,4405 ; v1(4134.8,3327.8) 4138.2,3327.8 4157.7,3347.3 4173.2,3347.3 U13.A8@4176,3344.4
CH2_SBU1_IGN: Q3.1 R37.2 R39.2 U21.117 | length 203
  Top Layer w10: R39.2@3136.6,4235 3154,4217.6 3249.1,4217.6 3255.5,4224.1 3255.5,4232.9 R37.2@3257.6,4235 3293.3,4270.7 Q3.1@3293.3,4282.6
CH2_SBU1_RELAY: Q3.3 R38.2 R42.2 U21.120 | length 202.4
  Top Layer w10: R38.2@3136.6,4405 3149.7,4405 3167.1,4422.4 3248.1,4422.4 3254.5,4415.9 3254.5,4407.1 R42.2@3256.6,4405 3256.6,4394.1 Q3.3@3293.3,4357.4
CH2_SBU2: R63.2 R64.2 R98.2 U13.B8 | length 246.2
  Top Layer w10: U13.B8@4231.1,3275.5 4231.6,3275 v1(4284.8,3275) ; R64.2@4291.1,4490 4291.1,4494.3 4264.2,4521.2 4264.2,4628.8 4291.1,4655.7 R63.2@4291.1,4660
CH2_SBU2_IGN: Q7.1 R62.2 R65.2 U21.76 | length 1563.6
  Top Layer w10: Q7.1@4194.4,4612.4 4230.1,4648.1 R65.2@4230.1,4660 4232.2,4662.1 4232.2,4670.9 4238.6,4677.4 4320.6,4677.4 4338,4660 R62.2@4351.1,4660 4353.2,4662.1 4353.2,4670.9 4360.6,4678.4 v1(4360.6,4693)
  Inner1 w10: v1(3521.1,4677.2) 3531.7,4677.2 3552.9,4698.4 3964.4,4698.4 4015.5,4749.5 4015.5,4780.8 4129.8,4895 4334.8,4895 4360.6,4869.2 v1(4360.6,4693)
  Bottom Layer w10: U21.76@3454.3,4830.2 3454.3,4730.1 3507.2,4677.2 v1(3521.1,4677.2)
CH2_SBU2_RELAY: Q7.3 R61.2 R66.2 U21.78 | length 2737.6
  Top Layer w10: Q7.3@4194.4,4537.6 4231.1,4500.9 R66.2@4231.1,4490 4233.2,4487.9 4233.2,4479.1 4239.6,4472.6 ; v1(4222.3,4455) 4239.6,4472.3 4239.6,4472.6 ; R61.2@4351.1,4490 4338,4490 4320.6,4472.6 4239.6,4472.6
  Inner1 w10: v1(3493.8,4752) 3493.8,4731.6 3376.8,4614.5 3376.8,4595.5 3390.2,4582 3409.3,4582 3422.8,4595.5 3473,4595.5 3557.5,4680 3809.8,4680 3840.8,4649 3840.8,4383.5 3831.8,4374.5 3831.8,4355.5 3845.2,4342 3864.3,4342 3877.8,4355.5 3877.8,4552 3869.8,4560 3869.8,4645.2 3894.6,4670 4054.3,4670 4080.8,4696.5 4080.8,4801 4146.7,4867 4307.8,4867 4329.8,4845 4329.8,4730 4319.8,4720 4319.8,4552.4 v1(4222.3,4455)
  Bottom Layer w10: U21.78@3493.7,4830.2 3493.8,4830.1 v1(3493.8,4752)
CH3_D_N: U14.A7 U14.B7 U19.6 | length 1443.8
  Top Layer w10: v1(3339.8,3300) 3331.7,3291.9 3330.3,3291.9 3320.7,3282.4 3297.3,3282.4 3264.9,3314.8 U14.B7@3248.4,3314.8 3199.9,3314.8 3178.3,3336.5 3178.3,3564.3 3129.8,3612.9 3129.8,3830 3157.2,3857.4 3159.2,3857.4 3178.3,3876.6 3178.3,3897.4 3326.2,4045.3 3326.2,4193.4 3464.8,4331.9 U19.6@3562,4331.9
CH3_D_P: U14.A6 U14.B6 U19.7 | length 1438.9
  Top Layer w10: v1(3210.1,3291.8) 3245.1,3291.8 U14.B6@3248.4,3295.2 ; U14.A6@3303.5,3324.6 3288,3324.6 3278.8,3333.8 3278.8,3436.8 3284.4,3442.4 3316.7,3442.4 3335.8,3461.6 3335.8,3488.6 3316.7,3507.7 3250.3,3507.7 3192.3,3565.7 3192.3,3575.1 3143.8,3623.6 3143.8,3824.2 3163,3843.4 3165,3843.4 3192.3,3870.8 3192.3,3891.5 3340.2,4039.5 3340.2,4187.6 3464.9,4312.3 U19.7@3562,4312.3
CH3_IMON: R85.1 U17.19 U21.52 | length 57.2
  Top Layer w10: R85.1@3533.5,3326.1 3537,3329.6 U17.19@3537,3381.9
CH3_PWR_EN: U17.14 U21.43
CH3_SBU1: R45.2 R46.2 R94.2 U14.A8 | length 230.1
  Top Layer w10: R45.2@3196.6,4455 3196.6,4459.3 3223.6,4486.2 3223.6,4593.8 3196.6,4620.7 R46.2@3196.6,4625 ; U14.A8@3303.5,3265.6 3336.4,3265.6 v1(3339.8,3269)
CH3_SBU1_IGN: Q4.1 R44.2 R47.2 U21.82 | length 716.6
  Top Layer w10: R44.2@3136.6,4455 3149.7,4455 3167.1,4437.6 3249.1,4437.6 3255.5,4444.1 3255.5,4452.9 R47.2@3257.6,4455 3257.6,4466.9 Q4.1@3293.3,4502.6 3302.4,4502.6 3317,4517.2 3372.4,4517.2 3436.8,4581.6 3436.8,4637 3500,4700.2 3555.4,4700.2 3566.5,4711.3 3566.5,4743.2 v1(3566.3,4743.4)
  Bottom Layer w10: v1(3566.3,4743.4) 3566.8,4743.8 3566.8,4787 3572.4,4792.7 U21.82@3572.4,4830.2
CH3_SBU1_RELAY: Q4.3 R43.2 R48.2 U21.81 | length 658.2
  Top Layer w10: R43.2@3136.6,4625 3149.7,4625 3167.1,4642.4 3248.1,4642.4 3254.5,4635.9 3254.5,4627.1 R48.2@3256.6,4625 3256.6,4614.1 Q4.3@3293.3,4577.4 3412.8,4577.4 3422.8,4587.4 3422.8,4648 3499.3,4724.5 v1(3542.8,4724.5)
  Bottom Layer w10: v1(3542.8,4724.5) 3542.8,4782.7 3552.8,4792.7 U21.81@3552.8,4830.2
CH3_SBU2: R69.2 R70.2 R95.2 U14.B8 | length 233.2
  Top Layer w10: v1(3209.8,3340) 3228.4,3340 3230.1,3338.3 3244.6,3338.3 U14.B8@3248.4,3334.5 ; R70.2@4291.1,4250 4291.1,4254.3 4264.2,4281.2 4264.2,4388.8 4291.1,4415.7 R69.2@4291.1,4420
CH3_SBU2_IGN: Q8.1 R68.2 R71.2 U21.77 | length 2287.8
  Top Layer w10: Q8.1@4194.4,4372.4 4231.1,4409.1 R71.2@4231.1,4420 4233.2,4422.1 4233.2,4430.9 4239.6,4437.4 4320.6,4437.4 4338,4420 R68.2@4351.1,4420 4353.2,4422.1 4353.2,4430.9 4359.8,4437.5 v1(4359.8,4455)
  Inner1 w10: v1(3854.8,4365) 3854.8,4650 3889.2,4684.4 4048.9,4684.4 4062.3,4697.9 4062.3,4807.8 4135.6,4881 4323.5,4881 4344.7,4859.8 4344.7,4720 4337.6,4712.9 4337.6,4683.5 4359.8,4661.4 v1(4359.8,4455)
  Bottom Layer w10: U21.77@3474,4830.2 3470.8,4827 3470.8,4733.4 3499.2,4705 3529.8,4705 3544.1,4690.7 3544.1,4685.6 3544.1,4640.3 3712.7,4471.7 3712.7,4465.2 3741.1,4436.8 3741.1,4406 3770.3,4376.7 3801.2,4376.7 3802.9,4375 3844.8,4375 v1(3854.8,4365)
CH3_SBU2_RELAY: Q8.3 R67.2 R72.2 U21.83 | length 2693.7
  Top Layer w10: Q8.3@4194.4,4297.6 4231.1,4260.9 R72.2@4231.1,4250 4233.2,4247.9 4233.2,4239.1 4239.6,4232.6 4320.6,4232.6 4340,4252 R67.2@4348,4252 4350.1,4249.9 4350.1,4241 4359.8,4231.3 v1(4359.8,4215)
  Inner1 w10: v1(3644.8,4650) 3660.8,4666 3804,4666 3804,4640.2 3790.6,4626.8 3790.6,4376.8 3839.4,4328 3870.1,4328 3891.8,4349.7 3891.8,4638 3909.8,4656 4060.1,4656 4094.8,4690.7 4094.8,4795.1 4152.6,4853 4302,4853 4315.8,4839.2 4315.8,4735.8 4305.8,4725.8 4305.8,4558.2 4225.5,4478 4212.8,4478 4199.3,4464.5 4199.3,4445.5 4212.8,4432 4287.8,4432 4359.8,4360 v1(4359.8,4215)
  Bottom Layer w10: U21.83@3592.1,4830.2 3592.1,4702.6 v1(3644.8,4650)
CH4_D_N: U15.A7 U15.B7 U19.8 | length 927.3
  Top Layer w10: U15.A7@3303.5,3700.2 3273.9,3729.8 U15.B7@3248.4,3729.8 3188,3729.8 3157.8,3760 3157.8,3816.4 3206.3,3864.9 3206.3,3885.7 3354.3,4033.7 3354.3,4181.8 3465,4292.6 U19.8@3562,4292.6
CH4_D_P: U15.A6 U15.B6 U19.9 | length 779.5
  Top Layer w10: v1(3214.8,3705) 3228.7,3705 3230.1,3706.4 3244.7,3706.4 U15.B6@3248.4,3710.2 ; U15.A6@3303.5,3739.6 3300.8,3742.4 3285.2,3742.4 3278.8,3748.8 3278.8,3848.6 3285.2,3855 3314.2,3855 3368.3,3909 3368.3,4176 3465.2,4272.9 U19.9@3562,4272.9
CH4_IMON: R88.1 U18.19 U21.45 | length 50.3
  Top Layer w10: U18.19@3537.1,3708.7 3539.8,3706 R88.1@3539.8,3659.5
CH4_PWR_EN: U18.14 U21.44
CH4_SBU1: R51.2 R52.2 R101.2 U15.A8 | length 239.7
  Top Layer w10: R51.2@3196.6,4685 3196.6,4689.3 3223.6,4716.2 3223.6,4823.8 3196.6,4850.7 R52.2@3196.6,4860 ; U15.A8@3303.5,3680.6 3322.8,3680.6 3330.2,3688 3332.8,3688 v1(3339.8,3695)
CH4_SBU1_IGN: Q5.1 R50.2 R53.2 U21.84 | length 652.1
  Top Layer w10: R50.2@3136.6,4685 3134.5,4682.9 3149.8,4667.6 3249.1,4667.6 3257.6,4676.1 R53.2@3257.6,4685 3293.3,4720.7 Q5.1@3293.3,4732.6 3442,4732.6 3484.3,4774.9 3592.3,4774.9 v1(3621,4746.2)
  Bottom Layer w10: U21.84@3611.8,4830.2 3614.3,4827.7 3614.3,4827.6 3615,4826.9 3615,4789.5 3621,4783.5 v1(3621,4746.2)
CH4_SBU1_RELAY: Q5.3 R49.2 R54.2 U21.85 | length 625.3
  Top Layer w10: R49.2@3136.6,4860 3149.7,4860 3167.1,4877.4 3248.1,4877.4 3254.5,4870.9 3254.5,4862.1 R54.2@3256.6,4860 3256.6,4844.1 Q5.3@3293.3,4807.4 3347.8,4807.4 v1(3428.9,4888.5)
  Bottom Layer w10: v1(3428.9,4888.5) 3436.8,4880.6 3618.6,4880.6 3628.3,4870.9 3628.3,4833.4 U21.85@3631.5,4830.2
CH4_SBU2: R75.2 R76.2 R99.2 U15.B8 | length 292
  Top Layer w10: v1(3181.8,3783) 3181.8,3758 3195.9,3743.9 3228.2,3743.9 3230.1,3745.7 3244.7,3745.7 U15.B8@3248.4,3749.5 ; R76.2@4291.1,3995 4291.1,3999.3 4264.2,4026.2 4264.2,4133.8 4291.1,4160.7 R75.2@4291.1,4165
CH4_SBU2_IGN: Q9.1 R74.2 R77.2 U21.138 | length 202.4
  Top Layer w10: Q9.1@4194.4,4117.4 4194.4,4128.3 R77.2@4231.1,4165 4233.2,4167.1 4233.2,4175.9 4239.6,4182.4 4320.6,4182.4 4338,4165 R74.2@4351.1,4165
CH4_SBU2_RELAY: Q9.3 R73.2 R78.2 U21.139 | length 201.8
  Top Layer w10: Q9.3@4194.4,4042.6 4230.2,4006.8 R78.2@4230.2,3997 4232.3,3994.9 4232.3,3986 4240.7,3977.6 4320.6,3977.6 4338,3995 R73.2@4351.1,3995
GND: C1.1 C2.1 C3.2 C6.2 C7.1 C8.1 C9.2 C12.2 C13.1 C14.1 C15.1 C16.1 C17.1 C18.1 C19.1 C20.1 C21.1 C22.1 C23.1 C24.1 C25.1 C26.1 C27.1 C28.1 C29.1 C30.1 C31.1 C32.1 C33.1 C34.1 C35.1 C36.1 C37.1 C38.2 C39.1 C40.1 C41.1 C42.2 C43.1 C45.2 C46.1 C47.1 C48.1 C49.1 C50.1 C51.1 C52.1 C53.2 D2.2 J1.4 J1.5 LED1.1 LED2.1 LED3.1 LED4.1 LED5.3 LED5.4 LED6.3 LED6.4 LED7.3 LED7.4 LED8.3 LED8.4 LED9.3 LED9.4 LED10.3 LED10.4 LED11.3 LED11.4 LED12.3 LED12.4 LED13.2 LED14.2 LED15.2 LED16.2 Q2.2 Q3.2 Q4.2 Q5.2 Q6.2 Q7.2 Q8.2 Q9.2 R2.2 R3.2 R5.2 R9.1 R31.1 R32.1 R37.1 R42.1 R47.1 R48.1 R53.1 R54.1 R59.1 R60.1 R65.1 R66.1 R71.1 R72.1 R77.1 R78.1 R79.2 R80.2 R82.2 R83.2 R85.2 R86.2 R88.2 R89.2 R103.1 R115.2 R116.1 R117.2 R119.1 R123.2 SCREW1.1 SCREW2.1 SCREW3.1 SCREW4.1 U1.3 U2.3 U3.2 U3.9 U4.2 U4.9 U5.2 U5.9 U6.2 U6.9 U7.2 U8.2 U9.2 U10.2 U11.3 U11.15 U11.16 U12.1 U12.2 U12.3 U12.4 U12.5 U12.6 U12.A1 U12.A12 U12.B12 U13.1 U13.2 U13.3 U13.4 U13.5 U13.6 U13.A1 U13.A12 U13.B12 U14.1 U14.2 U14.3 U14.4 U14.5 U14.6 U14.A1 U14.A12 U14.B12 U15.1 U15.2 U15.3 U15.4 U15.5 U15.6 U15.A1 U15.A12 U15.B12 U16.3 U16.15 U16.16 U17.3 U17.15 U17.16 U18.3 U18.15 U18.16 U19.19 U21.14 U21.34 U21.141 U22.6 U22.10 U23.1 U23.2 U23.3 U23.4 U23.5 U23.6 U23.A1 U23.A12 U23.B1 U23.B12 | length 5866.2
  Top Layer w10: LED5.4@3113.3,4069.4 LED5.3@3140.9,4069.4 ; LED6.4@3113.3,4294.4 LED6.3@3140.9,4294.4 ; LED7.4@3113.3,4514.4 LED7.3@3140.9,4514.4 ; LED8.4@3113.3,4744.4 LED8.3@3140.9,4744.4 ; R31.1@3237.6,4015 3237.6,4039.2 3237.9,4039.5 3237.9,4097.9 ; R32.1@3237.6,4185 3237.6,4158.9 3237.9,4158.6 3237.9,4097.9 ; R42.1@3237.6,4405 3237.6,4319.6 ; R48.1@3237.6,4625 3237.6,4540 ; R54.1@3237.6,4860 3237.6,4800 3238.6,4799 3238.6,4774.5 ; R37.1@3238.6,4235 3237.6,4236 3237.6,4319.6 ; R47.1@3238.6,4455 3237.6,4456 3237.6,4540 ; R53.1@3238.6,4685 3238.6,4774.5 ; U23.B1@3258.4,5031.7 U23.6@3258.4,5010.1 3313.3,5010.1 3313.5,5009.8 ; U23.B12@3258.4,5248.3 U23.5@3258.4,5269.9 3306.5,5269.9 3313.5,5277 ; Q3.2@3293.3,4320 3238,4320 3237.6,4319.6 ; Q4.2@3293.3,4540 3237.6,4540 ; Q5.2@3293.3,4770 3288.8,4774.5 3238.6,4774.5 ; Q2.2@3293.6,4099 3292.5,4097.9 3237.9,4097.9 ; R116.1@3304.8,4845.5 3344.8,4845.5 R115.2@3345.3,4846 ; U23.A12@3313.5,5021.8 3313.5,5009.8 ; U23.A1@3313.5,5258.1 3313.5,5277 ; U17.16@3468.1,3411.4 U17.15@3468.1,3431.1 ; U18.16@3468.2,3738.2 U18.15@3468.2,3757.9 ; R86.2@3493.5,3307 R85.2@3533.5,3307 ; R89.2@3499.8,3640.5 R88.2@3539.8,3640.5 ; C8.1@3589.6,5123 3616.5,5123 ; R117.2@3604.2,4542.2 C52.1@3604.2,4586.2 ; C12.2@3615.7,5026 3616.5,5026.8 C9.2@3616.5,5066.8 ; C9.2@3616.5,5066.9 3616.5,5123 ; U19.19@3630.9,4105.6 3630.9,4089.1 3641.1,4078.8 3664.8,4078.8 3671.8,4071.8 3671.8,4025 3683,4013.8 C49.1@3709.5,4013.8 ; C13.1@3639.6,5123 3616.5,5123 ; C51.1@3649.2,4543.5 C45.2@3649.2,4586.9 ; C6.2@3691.5,5281.5 3730.2,5281.5 R5.2@3731.5,5282.8 R3.2@3731.5,5237.8 3779.5,5237.8 D2.2@3784.1,5242.3 ; C42.2@3700.6,3960 3709.5,3968.9 C49.1@3709.5,4013.8 ; C7.1@3728,5357.3 ccw(c3726.6,5358.7) 3728.6,5358.7 C2.1@3728.6,5457 ; C50.1@3754.2,4026.9 3741.1,4013.8 C49.1@3709.5,4013.8 ; U16.16@3791.9,3411.4 U16.15@3791.9,3431.1 ; U11.16@3794.1,3738.2 U11.15@3794.1,3757.9 ; R83.2@3819.1,3307.2 3858,3307.2 R82.2@3858.6,3307.7 ; R79.2@3825.8,3641.6 3864.6,3641.6 R80.2@3866.3,3640 ; C25.1@3843.2,4857.7 3842.4,4856.9 C15.1@3641.3,4856.9 3643.2,4854.9 C21.1@3643.2,4814.3 C23.1@3723.2,4814.3 C20.1@3763.2,4814.3 C17.1@3803.2,4814.3 3841.4,4814.3 C14.1@3844.8,4810.9 ; C53.2@3853.8,4586.5 3854.2,4586.2 C46.1@3854.2,4543.5 ; C3.2@3909.8,5075.8 3967.8,5075.8 J1.4@4047.6,4996 J1.5@4185.4,4996 ; C48.1@3967.6,4432.7 3979.9,4420.5 3979.9,4417.5 3988.7,4408.8 R119.1@3988.7,4387.7 R123.2@3988.7,4347.7 ; U13.A1@4176,3186.9 4176,3155 U13.1@4196.1,3134.9 U13.4@4353.5,3134.9 ; U13.A12@4176,3423.2 4196.9,3423.2 ; Q9.2@4194.4,4080 4248.5,4080 4250.1,4078.3 ; Q8.2@4194.4,4335 4249.2,4335 4250.1,4336 ; Q7.2@4194.4,4575 4249.1,4575 ; Q6.2@4194.4,4810 4194.9,4810.5 4250.1,4810.5 ; U13.2@4196.1,3475.1 4196.1,3424 4196.9,3423.2 ; U12.1@4196.1,3554.9 4231.1,3590 U12.5@4231.1,3595.1 U12.B12@4231.1,3616.7 ; U13.6@4231.1,3434.9 4225.4,3429.2 4212.8,3429.2 4206.8,3423.2 4196.9,3423.2 ; R65.1@4249.1,4660 4249.1,4575 ; R60.1@4249.1,4725 4250.1,4726 4250.1,4810.5 ; R78.1@4249.2,3997 4250.1,3997.9 4250.1,4078.3 ; R77.1@4250.1,4165 4250.1,4078.3 ; R72.1@4250.1,4250 4250.1,4336 ; R71.1@4250.1,4420 4250.1,4336 ; R66.1@4250.1,4490 4249.1,4491 4249.1,4575 ; R59.1@4250.1,4895 4250.1,4810.5 ; LED11.3@4346.8,4360.6 LED11.4@4374.4,4360.6 ; LED10.3@4346.8,4595.6 LED10.4@4374.4,4595.6 ; LED9.3@4346.8,4835.6 LED9.4@4374.4,4835.6 ; 3313.5,5009.8 3313.5,4990 U23.2@3293.5,4969.9 U23.3@3136,4969.9 U23.4@3136,5310.1 U23.1@3293.5,5310.1 3313.5,5290 3313.5,5277
  Bottom Layer w10: U21.34@3434.6,3979.8 3437.8,3976.6 3437.8,3939.1 3474.8,3902.2 C36.1@3474.8,3870.8 ; C39.1@3764.8,3783.5 3799,3783.5 C38.2@3809.8,3794.2 3813.1,3797.6 3820.7,3797.6 3827.1,3804 3827.1,3811.6 3854,3838.5 C31.1@3964.8,3838.5 ; C32.1@4300.6,4085 4300.6,4094.3 4316.2,4110 4316.2,4198 ; R103.1@4309.3,4205 4316.2,4198 ; C37.1@4381.3,4110 4381.3,4156.8 4360.7,4177.4 4353.1,4177.4 C41.1@4349.8,4180.8 4333.5,4180.8 4316.2,4198
HUB_SCL: R120.2 U19.41 U21.66 | length 932.5
  Top Layer w10: v1(3879.8,4297.9) 3894.5,4297.9 3899.8,4292.6 U19.41@3916.3,4292.6 3957.5,4292.6 R120.2@3969.7,4304.8
  Bottom Layer w10: U21.66@3314.6,4631.4 3473.7,4631.4 3624.8,4480.4 3624.8,4427.5 3807.4,4244.9 3889.3,4244.9 3902.8,4258.4 3902.8,4277.4 3889.3,4290.9 3886.8,4290.9 v1(3879.8,4297.9)
HUB_SDA: R121.2 U19.40 U21.67 | length 857.2
  Top Layer w10: v1(3879.8,4267.9) 3894.8,4267.9 3899.8,4272.9 U19.40@3916.3,4272.9 3961.2,4272.9 R121.2@3970.2,4263.9
  Bottom Layer w10: U21.67@3309.8,4654.3 3314,4650 3474.9,4650 3638.8,4486.2 3638.8,4433.3 3797.2,4274.9 3872.8,4274.9 v1(3879.8,4267.9)
LED_B: R93.2 U21.1
LED_G: R92.2 U21.2
LED_R: R91.1 U21.3
PH0: C42.1 U21.25 X1.1 | length 69.8
  Top Layer w10: X1.1@3616.4,3977.4 3661.5,3977.4 C42.1@3679,3960
PH1: C43.2 U21.26 X1.3 | length 53.5
  Top Layer w10: C43.2@3520.6,4035 3523,4032.6 X1.3@3573.1,4032.6
SD_CLK: R114.2 U21.111 | length 960.1
  Top Layer w10: v1(4038.5,4771.3) 4079,4811.7 4109.8,4811.7 4178.4,4880.4 4187.8,4880.4 4256,4948.6 v1(4266.2,4948.6)
  Bottom Layer w10: v1(4038.5,4771.3) 4066.3,4771.3 4124.3,4713.3 4161.8,4713.3 U21.111@4165,4710.1 ; R114.2@4101.7,5387.6 4101.7,5378.1 4243.4,5236.4 4243.4,4971.4 v1(4266.2,4948.6)
SD_CMD: R113.2 U21.114 | length 757.9
  Bottom Layer w10: R113.2@4101.7,5307.6 4229.3,5179.9 4229.3,4736.9 4215.3,4722.8 4215.3,4663.9 4205.7,4654.3 4168.2,4654.3 U21.114@4165,4651.1
SD_D0: R109.2 U21.95 | length 1707.9
  Bottom Layer w10: U21.95@3828.3,4830.2 3828.3,5097.6 3719,5207 3563.2,5207 3479.8,5290.4 3479.8,5381 3452.6,5408.2 3452.6,5492.1 3459,5498.5 3936.2,5498.5 3944.7,5490.1 3969.9,5490.1 3969.9,5531.5 3976.3,5537.9 4060,5537.9 4113.6,5484.3 4113.6,5483.5 4118.6,5478.5 4118.6,5456.7 4101.7,5439.7 R109.2@4101.7,5427.6
SD_D1: R110.2 U21.96 | length 1513.1
  Bottom Layer w10: U21.96@3848,4830.2 3844.8,4833.4 3844.8,5100.9 3724.8,5221 3569,5221 3495.5,5294.5 3495.5,5372.1 3586,5462.6 3881.2,5462.6 3949.9,5394 4001.3,5394 4065.7,5458.4 4065.7,5478.5 4072.1,5485 4093.2,5485 4099.6,5478.5 4099.6,5469.7 R110.2@4101.7,5467.6
SD_D2: R111.2 U21.109 | length 518.3
  Bottom Layer w10: R111.2@4101.7,5227.6 4101.7,5215.5 4118.6,5198.5 4118.6,4998.8 4101.7,4981.9 4101.7,4812.8 U21.109@4165,4749.5
SD_D3: R112.2 U21.110 | length 627.6
  Bottom Layer w10: R112.2@4101.7,5267.6 4215.3,5154 4215.3,4742.7 4205.7,4733 4168.2,4733 U21.110@4165,4729.8
STM_D_N: U19.55 U21.100 | length 549.7
  Top Layer w10: U19.55@3768.7,4459.9 3768.7,4443.4 3797,4415 v1(3813.6,4415)
  Bottom Layer w10: v1(3813.6,4415) 3838.2,4415 3916.8,4493.6 3916.8,4554.5 3926.8,4564.5 U21.100@3926.8,4830.2
STM_D_P: U19.56 U21.101 | length 616.8
  Top Layer w10: U19.56@3749,4459.9 3749.8,4459.1 3749.8,4429.8 v1(3764,4415.5)
  Bottom Layer w10: v1(3764,4415.5) 3788.8,4390.7 3833.8,4390.7 3930.8,4487.8 3930.8,4548.7 3940.8,4558.7 3940.8,4609.8 3946.5,4615.4 U21.101@3946.5,4830.2
USB_D_N: U19.58 U23.A7 U23.B7 | length 1261.9
  Top Layer w10: v1@3206.6,5168.4 3225.3,5168.4 3243.9,5149.8 U23.B7@3258.4,5149.8 3283.9,5149.8 U23.A7@3313.5,5120.2 ; U19.58@3709.6,4459.9 3709.6,4443.4 3713,4440.1 v1(3713,4425.1)
  Bottom Layer w10: v1@3206.6,5168.4 3226.5,5168.4 3241.2,5183 3359.3,5183 3372.8,5169.5 3372.8,5150.5 3359.8,5137.5 3359.8,4950.6 3329.8,4920.6 3329.8,4834.8 3698.7,4465.9 3698.7,4456.1 3713,4441.8 v1(3713,4425.1)
  other v1: 3212.2,5168.4
USB_D_P: U19.59 U23.A6 U23.B6 | length 1168.3
  Top Layer w10: v1@3204.8,5135 3228.6,5135 3233.4,5130.1 U23.B6@3258.4,5130.1 ; U23.A6@3313.5,5159.6 3349.4,5159.6 v1(3349.8,5160) ; v1(3682.1,4426.2) 3690,4434 U19.59@3690,4459.9
  Bottom Layer w10: v1@3204.8,5135 3306.8,5135 3315.8,5126 ; v1(3349.8,5160) 3315.8,5126 ; v1(3682.1,4426.2) 3682.1,4462.7 3315.8,4829 3315.8,4926.4 3345.8,4956.4 3345.8,4983.4 3315.8,5013.4 3315.8,5126
  other v1: 3212.2,5135
VBUS: C48.2 R122.1 U23.A4 U23.A9 U23.B4 U23.B9 | length 1678.7
  Top Layer w10: U23.A4@3313.5,5199 3310.8,5196.2 3295.2,5196.2 3288.2,5189.2 U23.B9@3258.4,5189.2 3254.7,5193 3197,5193 3187,5183 3187,5092 3197,5082 3234.3,5082 3239.3,5087 3254.7,5087 U23.B4@3258.4,5090.8 3288.1,5090.8 3295.2,5083.7 3310.7,5083.7 U23.A9@3313.5,5080.9 3316.3,5078.1 3331.9,5078.1 3338.3,5071.6 3338.3,5061.5 3663.7,4736.1 4034.6,4736.1 v1(4038.3,4739.7) ; v1(3999.8,4470) 3999.8,4433.7 C48.2@4000.7,4432.7 4029.2,4404.3 R122.1@4029.2,4367.2
  Bottom Layer w10: v1(3999.8,4470) 3954.8,4515 3954.8,4604 4009.8,4658.9 4009.8,4711.2 v1(4038.3,4739.7)
VBUS_DET: R122.2 R123.1 U19.44 | length 128
  Top Layer w10: U19.44@3916.3,4351.6 R123.1@3965.1,4351.6 ; R123.1@3969.7,4347.7 3971.7,4345.7 3971.7,4336.8 3978.2,4330.4 4011.3,4330.4 R122.2@4029.2,4348.2
VDD18PLL: C51.2 C52.2 U19.62 | length 191.5
  Top Layer w10: C52.2@3604.2,4619.3 3616.4,4607 3619.3,4607 3631.8,4594.6 3631.8,4521.9 3634.7,4521.9 ; U19.62@3630.9,4459.9 3630.9,4518.1 3634.7,4521.9 ; C51.2@3649.2,4521.9 3634.7,4521.9
VDDA: C36.2 L8.2 U21.35 U21.36 | length 202.4
  Bottom Layer w10: U21.36@3395.3,3979.8 U21.35@3415,3979.8 3417.3,3977.4 L8.2@3417.3,3860 3456.4,3860 3463.8,3852.6 3471.4,3852.6 C36.2@3474.8,3849.2
VDDLDO: C37.2 C39.2 C40.2 C41.2 L7.1 U21.17 U21.68 U21.70 U21.103 U21.105 U21.143 | length 459.3
  Bottom Layer w10: C39.2@3764.8,3816.5 3769.3,3821.1 L7.1@3769.3,3871.1 ; L7.1@3768.2,3870 L7.1@3769.3,3871.1 ; U21.17@3769.3,3979.8 L7.1@3769.3,3871.1 ; U21.143@4165,4080.2 4168.2,4077 4205.7,4077 4221.9,4060.8 C40.2@4349.8,4060.8 4349.8,4108.5 C37.2@4348.2,4110 4349.8,4111.5 C41.2@4349.8,4159.2
VLXSMPS: C38.1 L7.2 U21.15 | length 170.6
  Bottom Layer w10: U21.15@3808.7,3979.8 3808.7,3877.4 L7.2@3801.3,3870 3809.8,3861.5 C38.1@3809.8,3815.8
pads on no net: U11.1 U11.2 U11.5 U11.6 U11.7 U11.8 U11.9 U11.10 U11.12 U11.13 U11.18 U11.20 U11.21 U12.A5 U12.B1 U12.B5 U13.A5 U13.B1 U13.B5 U14.A5 U14.B1 U14.B5 U15.A5 U15.B1 U15.B5 U16.1 U16.2 U16.5 U16.6 U16.7 U16.8 U16.9 U16.10 U16.12 U16.13 U16.18 U16.20 U16.21 U17.1 U17.2 U17.5 U17.6 U17.7 U17.8 U17.9 U17.10 U17.12 U17.13 U17.18 U17.20 U17.21 U18.1 U18.2 U18.5 U18.6 U18.7 U18.8 U18.9 U18.10 U18.12 U18.13 U18.18 U18.20 U18.21 U19.11 U19.12 U19.14 U19.15 U19.16 U19.17 U19.18 U19.20 U19.21 U19.22 U19.23 U19.24 U19.26 U19.27 U19.28 U19.29 U19.30 U19.31 U19.32 U19.33 U19.34 U19.35 U19.36 U19.37 U19.38 U19.39 U19.42 U19.47 U19.48 U19.49 U19.50 U19.51 U19.53 U19.54 U19.65 U20.2 U20.4 U21.4 U21.5 U21.6 U21.9 U21.10 U21.11 U21.12 U21.18 U21.20 U21.27 U21.33 U21.39 U21.40 U21.41 U21.46 U21.48 U21.49 U21.51 U21.53 U21.54 U21.55 U21.57 U21.58 U21.59 U21.60 U21.61 U21.62 U21.63 U21.64 U21.69 U21.74 U21.75 U21.80 U21.86 U21.87 U21.88 U21.89 U21.93 U21.94 U21.97 U21.98 U21.99 U21.102 U21.104 U21.107 U21.108 U21.118 U21.124 U21.125 U21.126 U21.127 U21.128 U21.140 U23.A2 U23.A3 U23.A8 U23.A10 U23.A11 U23.B2 U23.B3 U23.B8 U23.B10 U23.B11 X1.2 X1.4

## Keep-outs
Board Outline Layer:
  lines w10: 3133.5,5559 ccw(c3133.5,5480.3) 3054.8,5480.3 3054.8,3078.7 ; 3133.5,5559.1 4354,5559.1 ; 4354,5559 cw(c4354,5480.3) 4432.7,5480.3 4432.7,3078.7 cw(c4354,3078.7) 4354,3000 3133.5,3000 cw(c3133.5,3078.7) 3054.8,3078.7 ; 3054.8,3078.7 3054.8,3078.7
